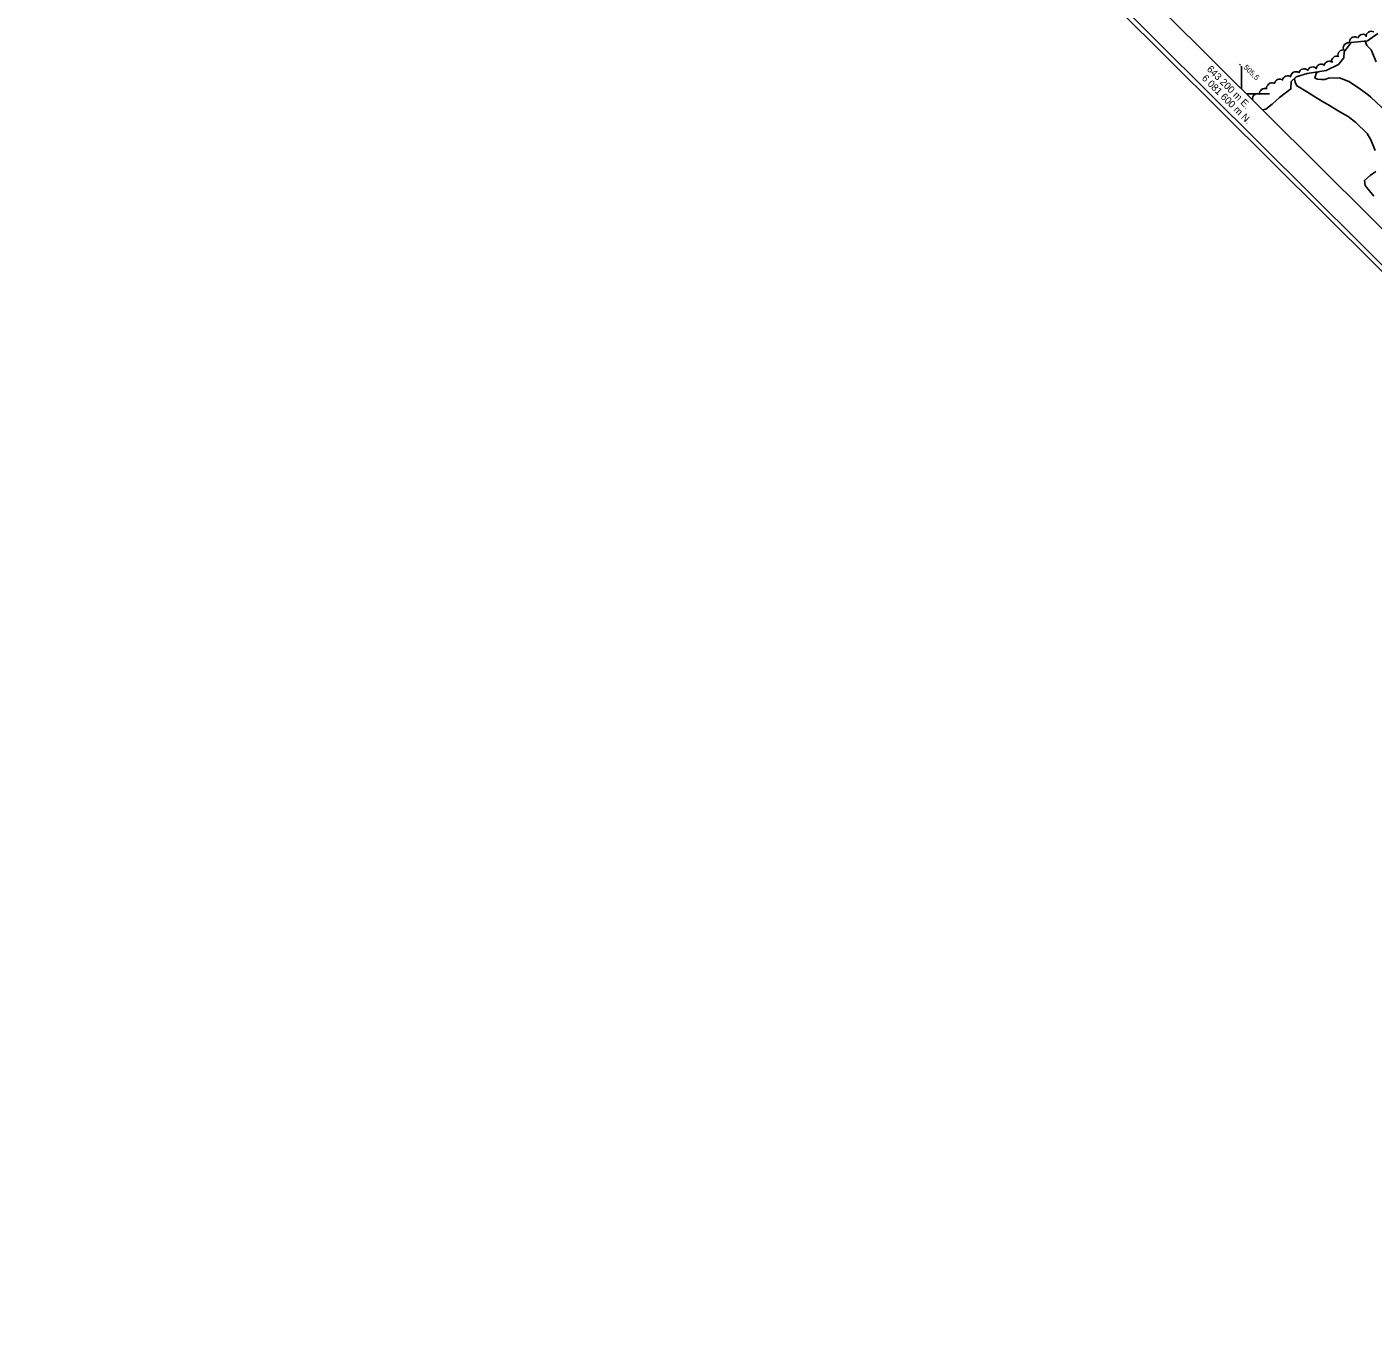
# Model space of a CAD drawing. Extents: x 642515 to 647219, y 6080136 to 6084356.
# Drawn here: x 642515 to 643274, y 6080896 to 6081638 of the extents above; entities that cross this region are included whole.
import ezdxf

# ---------------------------------------------------------------- set-up
doc = ezdxf.new("R2010")
doc.units = 0
for name, color, linetype in [('Level 1', 7, 'Continuous'), ('Level 2', 7, 'Continuous'), ('Level 3', 7, 'Continuous'), ('Level 44', 7, 'Continuous'), ('Level 57', 7, 'Continuous'), ('Level 60', 7, 'Continuous'), ('Level 61', 7, 'Continuous')]:
    doc.layers.add(name, color=color, linetype=linetype)

msp = doc.modelspace()

# ---------------------------------------------------------------- linework, layer by layer
at = {"layer": 'Level 1'}
for points in [[(643255.32, 6081609.04), (643249.17, 6081608.91), (643247.06, 6081608.22), (643244.91, 6081608.16), (643242.9, 6081608.28), (643241.5, 6081608.92), (643242.22, 6081611.6), (643243.42, 6081612.63)], [(643288.34, 6081583.99), (643273.09, 6081598.12), (643271.74, 6081599.32), (643266.7, 6081603.17), (643260.55, 6081607.12), (643255.32, 6081609.04)]]:
    msp.add_lwpolyline(points, dxfattribs=at)
at = {"layer": 'Level 2'}
for points in [[(643276.04, 6081618.15), (643273.19, 6081624.85), (643270.7, 6081627.33), (643269.79, 6081629.81)], [(643232.95, 6081603.67), (643231.21, 6081604.6), (643230.27, 6081606.61), (643229.99, 6081608.43), (643230.1, 6081608.89)], [(643275.46, 6081568.02), (643272.97, 6081574.08), (643270.97, 6081577.62), (643264.48, 6081583.9), (643260.26, 6081587.29), (643255.44, 6081590), (643248.78, 6081594.03), (643245.78, 6081595.75), (643242.28, 6081597.91), (643237.28, 6081601.09), (643235.45, 6081602.08), (643232.95, 6081603.67)], [(643274.63, 6081542.41), (643269.91, 6081548.32), (643269.4, 6081551.16), (643272.56, 6081554.09), (643275.93, 6081556.23)]]:
    msp.add_lwpolyline(points, dxfattribs=at)
at = {"layer": 'Level 3'}
msp.add_line((643198.91, 6081616.8), (643199.48, 6081616.24), dxfattribs=at)
at = {"layer": 'Level 44'}
for centre, start, end in [((643263.95, 6081629.23), 66.1435, 186.12144), ((643268.53, 6081630.71), 43.21313, 163.19107), ((643273.29, 6081632.38), 63.09595, 183.0739), ((643257.46, 6081621.9), 76.23057, 196.20852), ((643260.46, 6081625.94), 88.8162, 208.79415), ((643245.01, 6081613.78), 51.05223, 171.03018), ((643249.67, 6081615.6), 51.657, 171.63494), ((643253.86, 6081618.39), 70.76076, 190.7387), ((643226.21, 6081607.32), 52.52873, 172.50667), ((643230.7, 6081609.58), 57.43586, 177.4138), ((643235.36, 6081611.2), 46.93776, 166.9157), ((643240.22, 6081612.25), 41.84079, 161.81874), ((643213.25, 6081600.19), 67.78213, 187.76008), ((643217.2, 6081603.25), 67.78213, 187.76008), ((643221.59, 6081605.4), 52.52873, 172.50667), ((643209.21, 6081597.22), 65.24918, 185.22713)]:
    msp.add_arc(centre, 3, start, end, dxfattribs=at)
at = {"layer": 'Level 57'}
msp.add_lwpolyline([(643211.97, 6081591.08), (643213.68, 6081591.36), (643217.34, 6081594.29), (643221.42, 6081598.04), (643227.9, 6081602.82), (643228.12, 6081607.14), (643230.92, 6081609.62), (643237.03, 6081611.59), (643247.79, 6081613.35), (643254.7, 6081616.73), (643257.84, 6081620.43), (643258.04, 6081623.72), (643261.96, 6081629), (643271.11, 6081629.95), (643277.02, 6081634.23)], dxfattribs=at)
at = {"layer": 'Level 60'}
for p, q in [((643200, 6081602.98), (643200, 6081615.75)), ((643202.92, 6081600), (643215.76, 6081600))]:
    msp.add_line(p, q, dxfattribs=at)
for points in [[(643756.15, 6083509.1), (645893.11, 6081385.05), (644652.25, 6080135.58), (642514.75, 6082260.08)], [(642518.29, 6082260.09), (643756.16, 6083505.56), (645889.57, 6081385.04), (644651.74, 6080139.63)], [(643756.23, 6083485.06), (645517.55, 6081734.46), (644300.6, 6080509.08), (642538.79, 6082260.16)]]:
    msp.add_lwpolyline(points, close=True, dxfattribs=at)

# ---------------------------------------------------------------- texts
at = {"layer": 'Level 3'}
msp.add_text('505,5', height=3, rotation=315.59, dxfattribs=at).set_placement((643200.94, 6081614.76))
at = {"layer": 'Level 61'}
for s, p in [('6 081 600 m N.', (643177.38, 6081608.55)), ('643 200 m E.', (643180.19, 6081613.66))]:
    msp.add_text(s, height=4, rotation=315.17501, dxfattribs=at).set_placement(p)

doc.saveas('drawing.dxf')
